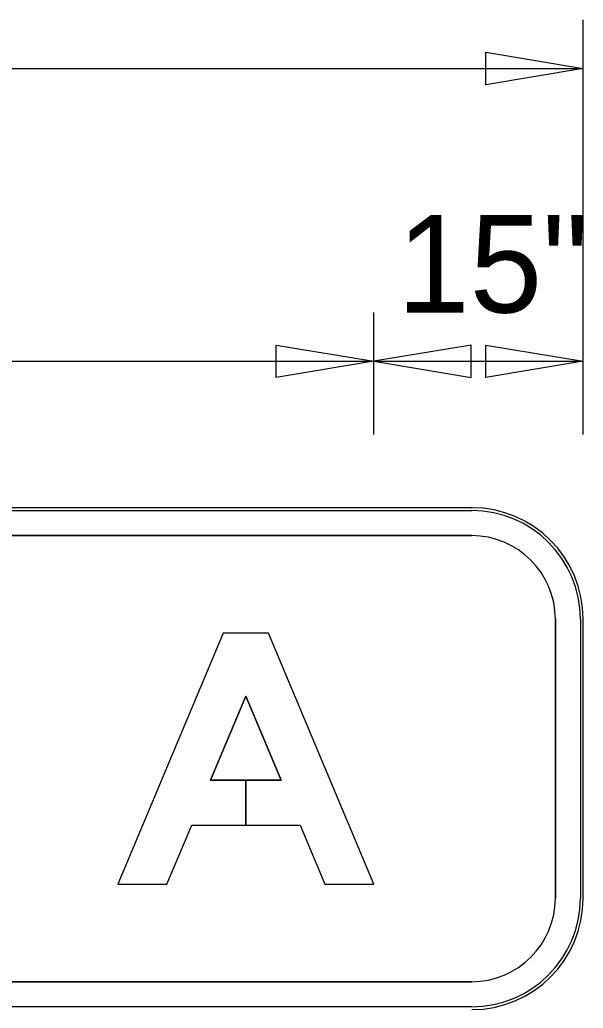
# Model space of a CAD drawing. Extents: x 2149934 to 2150188, y 145113 to 145238.
# Drawn here: x 2150104.66 to 2150108.03, y 145203.45 to 145209.36 of the extents above; entities that cross this region are included whole.
import ezdxf

# ---------------------------------------------------------------- set-up
doc = ezdxf.new("R2010")
doc.units = 0
for name, color, linetype in [('GSBWFILL', 7, 'Continuous'), ('GSCOLORFILL', 7, 'Continuous'), ('GSDIMS', 7, 'Continuous'), ('GSOUTLINE', 7, 'Continuous')]:
    doc.layers.add(name, color=color, linetype=linetype)

msp = doc.modelspace()

# ---------------------------------------------------------------- linework, layer by layer
at = {"layer": 'GSBWFILL'}
for p, q in [((2150107.362, 145206.4451), (2150095.6952, 145206.4451)), ((2150095.6952, 145206.2785), (2150107.362, 145206.2785)), ((2150107.862, 145205.7785), (2150107.862, 145204.1115)), ((2150108.0287, 145204.1115), (2150108.0287, 145205.7785)), ((2150107.362, 145203.6115), (2150095.6968, 145203.6115))]:
    msp.add_line(p, q, dxfattribs=at)
msp.add_lwpolyline([(2150106.2218, 145204.8174), (2150106.0112, 145204.8174), (2150106.0112, 145204.5474), (2150106.3352, 145204.5474), (2150106.4833, 145204.1949), (2150106.7761, 145204.1949), (2150106.1461, 145205.6949), (2150105.8761, 145205.6949), (2150105.2461, 145204.1949), (2150105.5389, 145204.1949), (2150105.687, 145204.5474), (2150106.0111, 145204.5474), (2150106.0111, 145204.8174), (2150105.8004, 145204.8174), (2150106.0111, 145205.3191)], close=True, dxfattribs=at)
for centre, radius, start, end in [((2150107.362, 145205.7785), 0.6667, 0, 90), ((2150107.362, 145205.7785), 0.5, 0, 90), ((2150107.362, 145204.1115), 0.6667, 270, 0), ((2150107.362, 145204.1115), 0.5, 270, 0)]:
    msp.add_arc(centre, radius, start, end, dxfattribs=at)
at = {"layer": 'GSCOLORFILL'}
for p, q in [((2150107.362, 145206.4451), (2150095.6952, 145206.4451)), ((2150107.362, 145206.4451), (2150095.6952, 145206.4451)), ((2150107.362, 145206.4451), (2150095.6952, 145206.4451)), ((2150095.6952, 145206.4285), (2150107.362, 145206.4285)), ((2150095.6952, 145206.2785), (2150107.362, 145206.2785)), ((2150107.862, 145205.7785), (2150107.862, 145204.1115)), ((2150108.012, 145205.7785), (2150108.012, 145204.1115)), ((2150108.0287, 145204.1115), (2150108.0287, 145205.7785)), ((2150108.0287, 145204.1115), (2150108.0287, 145205.7785)), ((2150108.0287, 145204.1115), (2150108.0287, 145205.7785)), ((2150107.362, 145203.6115), (2150095.6968, 145203.6115)), ((2150107.362, 145203.4615), (2150095.6953, 145203.4615))]:
    msp.add_line(p, q, dxfattribs=at)
msp.add_lwpolyline([(2150106.2218, 145204.8174), (2150106.0112, 145204.8174), (2150106.0112, 145204.5474), (2150106.3352, 145204.5474), (2150106.4833, 145204.1949), (2150106.7761, 145204.1949), (2150106.1461, 145205.6949), (2150105.8761, 145205.6949), (2150105.2461, 145204.1949), (2150105.5389, 145204.1949), (2150105.687, 145204.5474), (2150106.0111, 145204.5474), (2150106.0111, 145204.8174), (2150105.8004, 145204.8174), (2150106.0111, 145205.3191)], close=True, dxfattribs=at)
for centre, radius, start, end in [((2150107.362, 145205.7785), 0.6667, 0, 90), ((2150107.362, 145205.7785), 0.6667, 0, 90), ((2150107.362, 145205.7785), 0.6667, 0, 90), ((2150107.362, 145205.7785), 0.65, 0, 90), ((2150107.362, 145205.7785), 0.5, 0, 90), ((2150107.362, 145204.1115), 0.6667, 270, 0), ((2150107.362, 145204.1115), 0.6667, 270, 0), ((2150107.362, 145204.1115), 0.5, 270, 0), ((2150107.362, 145204.1115), 0.6667, 270, 0), ((2150107.362, 145204.1115), 0.65, 270, 0)]:
    msp.add_arc(centre, radius, start, end, dxfattribs=at)
at = {"layer": 'GSDIMS'}
for p, q in [((2150108.0287, 145208.6327), (2150108.0287, 145209.3619)), ((2150095.0285, 145209.0702), (2150108.0287, 145209.0702)), ((2150108.0287, 145206.8827), (2150108.0287, 145208.6327)), ((2150106.7761, 145206.8827), (2150106.7761, 145207.6119)), ((2150106.7761, 145206.8827), (2150106.7761, 145207.6119)), ((2150108.0287, 145206.8827), (2150108.0287, 145207.6119)), ((2150096.2786, 145207.3202), (2150106.7761, 145207.3202)), ((2150106.7761, 145207.3202), (2150108.0287, 145207.3202))]:
    msp.add_line(p, q, dxfattribs=at)
for points in [[(2150108.0287, 145209.0702), (2150107.4454, 145208.973), (2150107.4454, 145209.1674)], [(2150106.7761, 145207.3202), (2150106.1928, 145207.223), (2150106.1928, 145207.4174)], [(2150106.7761, 145207.3202), (2150107.3594, 145207.223), (2150107.3594, 145207.4174)], [(2150108.0287, 145207.3202), (2150107.4454, 145207.223), (2150107.4454, 145207.4174)]]:
    msp.add_lwpolyline(points, close=True, dxfattribs=at)
at = {"layer": 'GSOUTLINE'}
for p, q in [((2150107.362, 145206.4451), (2150095.6952, 145206.4451)), ((2150107.362, 145206.2785), (2150095.6952, 145206.2785)), ((2150107.862, 145204.1115), (2150107.862, 145205.7785)), ((2150108.0287, 145204.1115), (2150108.0287, 145205.7785)), ((2150095.6952, 145203.6115), (2150107.362, 145203.6115))]:
    msp.add_line(p, q, dxfattribs=at)
for points in [[(2150105.687, 145204.5474), (2150106.3352, 145204.5474), (2150106.4833, 145204.1949), (2150106.7761, 145204.1949), (2150106.1461, 145205.6949), (2150105.8761, 145205.6949), (2150105.2461, 145204.1949), (2150105.5389, 145204.1949)], [(2150106.2218, 145204.8174), (2150106.0111, 145205.3191), (2150105.8004, 145204.8174)]]:
    msp.add_lwpolyline(points, close=True, dxfattribs=at)
for centre, radius, start, end in [((2150107.362, 145205.7785), 0.6667, 0, 90), ((2150107.362, 145205.7785), 0.5, 0, 90), ((2150107.362, 145204.1115), 0.6667, 270, 0), ((2150107.362, 145204.1115), 0.5, 270, 0)]:
    msp.add_arc(centre, radius, start, end, dxfattribs=at)

# ---------------------------------------------------------------- texts
at = {"layer": 'GSDIMS'}
msp.add_text('15"', height=0.58333, dxfattribs=at).set_placement((2150106.9158, 145207.6119))

doc.saveas('drawing.dxf')
